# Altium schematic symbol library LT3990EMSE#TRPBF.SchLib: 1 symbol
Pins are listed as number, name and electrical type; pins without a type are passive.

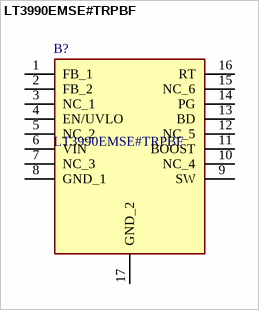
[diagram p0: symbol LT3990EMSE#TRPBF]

## LT3990EMSE#TRPBF
designator B?
Switching Voltage Regulators 60V, 350mA Step-Down Regulator with 2uA Quiescent Current and Integrated Diodes in MS16E; Manufacturer_Name: Analog Devices; Geometry.Height: 1.1mm
footprint SOP50P490X110-17N
pins: 1 FB_1, 2 FB_2, 3 NC_1, 4 EN/UVLO, 5 NC_2, 6 VIN, 7 NC_3, 8 GND_1, 9 SW, 10 NC_4, 11 BOOST, 12 NC_5, 13 BD, 14 PG, 15 NC_6, 16 RT, 17 GND_2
